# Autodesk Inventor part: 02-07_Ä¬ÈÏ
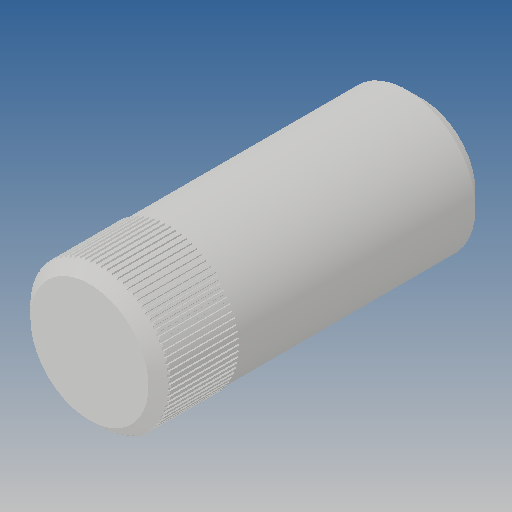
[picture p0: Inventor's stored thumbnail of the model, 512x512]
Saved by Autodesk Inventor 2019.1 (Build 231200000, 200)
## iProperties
Created: 2010-06
Part Number: 02-07_Ä¬ÈÏ
Material: Ogólny
Document SubType Name: Modeling
Designer: CADENGINEERING4
Density: 1 g/cm^3
Appearance: Domyślna
Author: CADENGINEERING4
Revision Number: ÈÎºÎ
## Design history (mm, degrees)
feature "NONE"
node "Bryła1"
